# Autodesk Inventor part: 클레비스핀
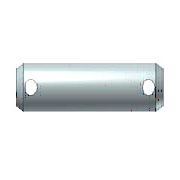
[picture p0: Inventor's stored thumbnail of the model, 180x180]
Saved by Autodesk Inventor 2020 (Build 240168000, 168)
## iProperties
Created: 2012-02
Part Number: 클레비스핀
Material: 강철
Description: 머리가 없는 클레비스 핀 B
Document SubType Name: Modeling
Standard: ISO 2340
Designer: mduedu
Standard Revision: Second edition 1986-11-01
Standards Organization: ISO
Language: ko-KR
Size Designation: B - 8 x 45
Categories: <MemberInstance><Categories><Category DisplayName="조임쇠" InternalName="e4da775c-781d-43d5-af7c-5136215cf5a6" Mnemonic="FSTN"><Category DisplayName="핀" InternalNa
Density: 7.85 g/cm^3
Appearance: 반광택
Mass: 14.9792 g
Surface Area: 11.4108 cm^2
Volume: 1.90818 cm^3
IsCustomPart: 1
Author: mduedu
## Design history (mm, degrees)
sketch "스케치1"
  geometry: L1 (-4.5, 0)-(-4.5, 4); L2 (-4.5, 4)-(35.5, 4); L3 (35.5, 4)-(35.5, 0); L4 (-4.5, 0)-(35.5, 0); L5 (0, -2)-(0, 5) reference; L6 (-13.5, 0)-(49.5, 0) reference; C1 r 1 at (-1, 0); C2 r 1 at (32, 0)
  constraints: 8 end point, 2 centre point, 2 perpendicular, 2 point on line, 1 collinear, 1 parallel, 1 tangent, 1 vertical
  dimensions: "d0" = 8 diameter of L2 L4 (= NND); "d1" = 40 distance of L1.end L2.end (= NLG); "d2" = 3.5 distance from line of L1 C1.centre (= DIST1); "d3" = 3.5 distance from line of L3 C2.centre (= DIST2); "d4" = 2 diameter of C1 (= BOR1); "d5" = 2 diameter of C2 (= BOR2)
revolve "본체" stored, may be unused: angle "d7" = 90 deg
extrude "구멍1" cut sketch "스케치1" extent not by distance; taper "d6" = 0 deg; stored distance "d8" = 10
extrude "구멍2" cut sketch "스케치1" extent not by distance; taper "d13" = 0 deg; stored distance "d14" = 10
workaxis "Work Axis1"
workaxis "Work Axis2"
workplane "Work Plane1"
node "작업 평면5"
body "Solid1"
chamfer "모따기2" distance "d9" = 2 (= PHH2); stored, may be unused: angle "d10" = 30 deg (= FAWI2), second distance "d40" = 2 (= PHH2)
chamfer "모따기1" distance "d11" = 2 (= PHH1); stored, may be unused: angle "d12" = 30 deg (= FAWI1), second distance "d41" = 2 (= PHH1)
other parameters: "NLG" = 40 [user parameter; used in 1 equation term], "NND" = 8 [user parameter; used in 1 equation term], "PHH1" = 2 [user parameter; used in 3 equation terms], "PHH2" = 2 (= PHH1) [user parameter; used in 2 equation terms], "FAWI1" = 30 deg [user parameter; used in 1 equation term], "FAWI2" = 30 deg [user parameter; used in 1 equation term], "DIST1" = 3.5 [user parameter; used in 4 equation terms], "DIST2" = 3.5 (= DIST1) [user parameter; used in 1 equation term], "BOR1" = 2 [user parameter; used in 4 equation terms], "BOR2" = 2 (= BOR1) [user parameter; used in 1 equation term], "d15" = 0, "d42" = 0, "d43" = 0, "d44" = -4.5 (= -0.5 x BOR1 - DIST1), "d45" = -4.5 (= -0.5 x BOR1 - DIST1), "d47" = 0, "d48" = 0, "d49" = 0, "d50" = 0, "d51" = 0, "d52" = 0
